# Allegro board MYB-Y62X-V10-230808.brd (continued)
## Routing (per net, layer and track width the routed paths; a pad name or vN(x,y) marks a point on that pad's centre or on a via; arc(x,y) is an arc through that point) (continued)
VDD_3V9: length 36.1
  TOP w0.381: R328.1 C177.1 v1(33.45,63.25)
  ART03 w0.381: v1(33.07,65.91) 33.45,65.53 v1(33.45,63.25)
  BOTTOM w0.381: R337.1 R336.1 ; R336.1 R342.1 R341.1 41.28,45.15 42.01,44.42 43.77,44.42 R340.1 R339.1 45.77,45.03 46.38,44.42 48.23,44.42 48.61,44.81 v1(48.61,48.97) ; R336.1 30.27,43.66 29.71,43.1 27.22,43.1 26.74,43.59 26.74,44.92 R338.1
  vias: v1(27.35,59.82) v1(27.35,59.18) v1(27.99,59.82) v1(27.99,59.18) v1(32.43,67.18) v1(32.43,66.55) v1(32.43,65.91) v1(33.07,67.18) v1(33.07,66.55) v1(44.75,59.31) v1(45.39,59.31) v1(46.02,59.31) v1(46.66,59.31) v1(46.66,58.67) v1(46.66,58.04)
VDD_5V: length 87
  TOP w0.203: U53.7 v1(151.81,49.78)
  TOP w0.381: R10.1 v1(34.46,29.9) ; v1(41.63,33.59) R13.1 40.62,33.66 R14.1 ; D59.1 v1(149.27,16.13) ; D58.1 147.62,15.88 v1(147.24,16.26) ; v1(130.6,22.73) 130.6,22.32 F3.2 131.62,22.32 v1(131.62,22.73) ; v1(125.55,24.21) 125.55,23.8 F2.2 124.53,23.8 v1(124.53,24.21) ; R531.1 144.77,51.33 145.21,51.77 147.82,51.77 148.64,50.95 152.35,50.95 152.77,50.53 C281.1 151.94,49.91 v1(151.81,49.78) ; R324.1 v1(43.23,62.74)
  ART03 w0.381: v1(43.23,62.74) 46.45,62.74 47.04,63.32 v1(47.04,66.93) ; v1(164.26,42.42) 163.75,42.93 161.72,42.93 160.42,44.22 158.85,44.22 154.61,48.46 153.36,48.46 152.04,49.78 v1(151.81,49.78)
  ART03 w0.508: v1(22.91,64.72) 22.65,64.97 21.71,64.97 20.95,65.74 20.95,68.99 19,70.94 19,78.41 21.26,80.67 v1(21.26,84.2)
  BOTTOM w0.381: v1(147.24,16.26) 147.62,15.88 C90.1 ; 48.43,39.24 R17.1 ; v1(74.82,97.16) 75.08,96.9 76.52,96.9 R21.1 ; R530.1 151.32,50.27 v1(151.81,49.78) ; v1(43.91,42.14) 43.71,41.94 43.71,34.24 43.06,33.59 v1(41.63,33.59)
  vias: v1(22.91,64.08) v1(23.54,64.72) v1(23.54,64.08) v1(24.15,64.74) v1(24.15,64.11) v1(43.91,42.75) v1(44.52,42.75) v1(44.52,42.14) v1(45.11,42.75) v1(45.11,42.14) v1(45.72,42.75) v1(45.72,42.14) v1(47.04,68.2) v1(47.04,67.56) v1(47.37,40.97) v1(47.37,40.36) v1(47.67,68.2) v1(47.67,67.56) v1(47.67,66.93) v1(47.98,40.97) v1(47.98,40.36) v1(55.93,26.92) v1(55.93,26.29) v1(56.56,26.92) v1(56.56,26.29) v1(70.99,98.83) v1(70.99,98.22) v1(71.62,98.83) v1(71.62,98.22) v1(111.43,100.46) v1(111.43,99.95) v1(111.93,100.46) v1(111.93,99.95) v1(164.26,41.91) v1(164.77,42.42) v1(164.77,41.91) v1(170.86,99.82) v1(171.62,99.82) v1(171.62,99.19) v1(171.62,98.55)
VDD_5V_SW:
  vias: v1(32.2,33.86) v1(32.86,33.86) v1(33.57,37.97) v1(33.57,37.39)
VDD_12V: length 44.5
  TOP w0.381: R4.1 45.13,76.33 45.89,77.09 v1(45.89,78.11) ; v1(36.57,32.69) 36.57,31.32 38.1,29.79 39.35,29.79 39.73,30.18 R11.1
  ART03 w0.381: v1(45.89,78.11) 45.26,78.74 44.34,78.74 40.79,82.3 36.37,82.3 35.84,81.76 v1(29.94,81.76)
  BOTTOM w0.381: v1(21.18,36.07) 21.21,36.04 26.51,36.04 30.96,31.6 35.48,31.6 v1(36.57,32.69)
  vias: v1(10.59,23.75) v1(10.59,23.24) v1(10.59,22.73) v1(11.1,23.75) v1(11.1,23.24) v1(11.1,22.73) v1(11.6,23.75) v1(11.6,23.24) v1(11.6,22.73) v1(12.11,23.75) v1(12.11,23.24) v1(12.11,22.73) v1(12.44,89.59) v1(12.44,88.95) v1(13.08,89.59) v1(13.08,88.95) v1(17.06,100.97) v1(17.06,100.33) v1(17.7,100.97) v1(17.7,100.33) v1(20.52,37.24) v1(20.52,36.65) v1(20.52,36.07) v1(21.18,37.24) v1(21.18,36.65) v1(22.14,84.2) v1(22.78,84.2) v1(29.28,82.91) v1(29.28,82.32) v1(29.28,81.74) v1(29.94,82.93) v1(29.94,82.35)
VDD_485_5V: length 2
  TOP w0.381: v1(133.02,110.24) 132.57,109.79 R267.1
  TOP w0.508: R279.1 v1(121.46,109.43)
  vias: v1(111.68,106.05) v1(111.68,105.41) v1(112.31,106.05) v1(112.31,105.41) v1(114.35,107.31) v1(114.35,106.81) v1(114.98,107.31) v1(127.05,107.31) v1(127.05,106.81) v1(127.68,107.31)
VDD_AUDIO_3V3: length 1.2
  TOP w0.254: v1(41.32,21.59) 41.45,21.72 U27.5
  vias: v1(38.35,25.73) v1(38.88,25.73) v1(39.42,26.26) v1(39.42,25.73)
VDD_BLE_3V3: length 56.4
  TOP w0.381: R74.1 R76.1 R72.1 R71.1 R69.1 R70.1 v2(41.64,109.54) 42.59,110.49 R77.1 ; R73.1 64.88,111.44 v2(64.56,111.12) 64.56,107.26 66.14,105.69 66.14,98.98 64.72,97.56 ; v2(56.43,93.34) C271.1 R511.1 54.66,93.92 Y6.4
  ART03 w0.381: v1(58.34,96.65) 58.34,96.39 56.43,94.49 v2(56.43,93.34)
  BOTTOM w0.381: v2(41.64,109.54) 43.23,111.12 v2(64.56,111.12)
VDD_CAN_5V:
  vias: v1(141.02,106.68) v1(141.65,106.68) v1(142.29,106.68) v1(142.29,106.05) v1(152.45,106.81) v1(153.08,106.81) v1(153.72,106.81) v1(153.72,106.17) v1(169.59,105.16) v1(170.23,105.16) v1(170.86,105.16) v1(171.5,105.16)
VDD_IN_GND:
  vias: v1(30.53,15.75) v1(30.53,15.11) v1(31.16,15.75) v1(31.16,15.11) v1(31.8,15.75) v1(31.8,15.11)
VDD_LVD_5V: length 11.6
  TOP w0.381: C79.1 21.86,89.59 C80.1 20.31,89.59 v1(19.85,90.05) Q3.3
  BOTTOM w0.381: v1(19.85,90.05) 19.85,88.78 20.49,88.14 20.49,86.74 19.86,86.11 18.72,86.11 18.08,85.47 v1(18.08,84.07)
  vias: v1(17.45,84.07) v1(17.45,83.44) v1(17.57,53.85) v1(17.57,53.21) v1(18.08,83.44) v1(18.21,53.85) v1(18.21,53.21)
VDD_MMC1_SD: length 10.3
  TOP w0.305: 79.97,105.17 C54.1
  TOP w0.381: v2(79.04,103.63) R36.1 R35.1 R34.1 ; R40.1 R39.1 R38.1 R37.1 82.07,104.29 81.07,105.28 FB1.2
  BOTTOM w0.381: v2(79.04,103.63) 79.04,104.65 v2(80.06,105.66)
  vias: v1(80.18,109.86) v1(80.18,109.22) v1(81.33,108.71) v2(80.44,105.92) v2(80.95,105.93)
VDD_PHY1_1V1: length 25.6
  TOP w0.203: U33.22 93.73,33.76 v1(93.79,33.81)
  BOTTOM w0.381: C211.1 92.85,32.84 91.79,31.78 88.24,31.78 86.84,33.17 86.84,39.48 v1(86.44,39.88)
  BOTTOM w0.508: C211.1 93.01,33.81 v1(93.79,33.81) 93.85,33.76 93.85,28.76 94.26,28.35 96.08,28.35 96.73,27.7 v1(96.73,27.18)
  vias: v1(85.37,39.88) v1(85.87,39.88) v1(96.16,27.2)
VDD_PHY1_3V3: length 25.1
  TOP w0.203: U33.30 90.07,36 v1(89.87,36.2) 89.67,36 U33.31
  TOP w0.381: R365.1 v1(82.89,40.01) ; R365.1 R370.1 ; R365.1 R364.1
  BOTTOM w0.381: v1(83.49,34.54) 83.44,34.54 81.01,36.97 81.01,39.46 81.56,40.01 v1(82.89,40.01) 83.68,40.79 86.66,40.79 87.6,39.85 87.6,36.27 88.38,35.49 C215.1 C216.1 90.13,35.94 v1(89.87,36.2)
  vias: v1(83.49,33.91) v1(83.99,34.16)
VDD_PHY2_1V1: length 26.8
  TOP w0.203: U37.22 117.03,33.76 v1(117.09,33.81)
  BOTTOM w0.381: v1(119.55,26.8) 119.55,29.31 117.93,30.94 117.93,32.97 v1(117.09,33.81) 116.31,33.81 C226.1 116.02,32.18 115.64,31.8 111.58,31.8 110.84,32.54 110.84,33.68 107.69,36.83 107.69,38.73 108.48,39.52 v1(108.48,40.03)
  BOTTOM w0.508: v1(109.65,40.03) v1(110.18,40.03)
  vias: v1(119.02,26.8)
VDD_PHY2_3V3: length 22.2
  TOP w0.203: U37.31 112.97,35.87 v1(113.19,36.09) 113.37,35.92 U37.30
  TOP w0.381: R405.1 R400.1 R399.1 105.33,39.31 v1(105.33,40.01)
  BOTTOM w0.381: v1(113.19,36.09) 113.42,35.86 C235.1 ; v1(103.64,37.59) v1(104.28,37.59) 104.34,37.65 104.34,39.37 104.97,40.01 v1(105.33,40.01) 105.33,40.23 105.84,40.74 108.63,40.74 109.06,40.31 109.06,39.22 108.28,38.43 108.28,37.21 110,35.49 C233.1
  BOTTOM w0.508: C233.1 C235.1
VDD_RTC:
  vias: v1(115.97,64.82) v1(116.53,64.82) v1(123.39,61.19) v1(124.05,61.19)
VDD_SOM_3V3: length 187.2
  TOP w0.381: R227.1 R231.1 R230.1 ; v2(142.39,46.41) 145.64,46.41 146.77,45.27 R222.1 R228.1 R223.1 R224.1 R225.1 R226.1 155.37,45.82 v2(155.14,46.05) ; R230.1 v1(129.59,39.4) ; R230.1 R220.1 R219.1 R218.1 R229.1 119.76,40.2 119.38,40.58 119.38,41.94 116.94,44.37 116.94,50.24 114.96,52.22 v2(109.98,52.22) ; v2(86.58,41.76) 84.88,41.76 83.92,40.79 80.9,40.79 75.69,35.59 65.25,35.59 63.88,34.21 v1(51.93,34.21) ; R217.1 R221.1 157.86,51.31 156.69,50.14 156.69,48.72 158.16,47.24 R216.1 158.8,46.51 159.64,45.67 v2(159.64,43.46)
  TOP w0.508: v1(104.99,81.88) U43.L43
  ART03 w0.381: v2(159.64,43.46) 159.2,43.03 156.97,43.03 155.14,44.86 v2(155.14,46.05) ; v2(109.98,52.22) 109.98,53.01 105.96,57.02 105.96,72.49 105.13,73.33 105.13,75.39 105.63,75.9 105.63,78.31 107.06,79.73 107.06,80.85 106.03,81.88 v1(104.99,81.88) ; v2(142.39,46.41) 141.3,46.41 134.29,39.4 v1(129.59,39.4)
  BOTTOM w0.381: v2(109.98,52.22) 105.33,47.57 90.85,47.57 90.32,48.11 88.13,48.11 87.47,47.45 87.47,42.65 v2(86.58,41.76) ; R573.1 v1(51.93,34.21)
VDD_SOM_5V: length 37.4
  TOP w0.381: v1(61.36,86.79) 58.77,86.79 47.04,75.06 39.44,75.06 38.78,75.72 R3.1
  BOTTOM w0.381: v1(66.77,92.35) 66.77,89.99 63.57,86.79 v1(61.36,86.79)
VDD_SOM_5V_R: length 10.8
  TOP w0.381: R8.1 44.95,79.63 R7.1 45.39,80.07 v2(45.39,80.52)
  ART03 w0.381: v2(45.39,80.52) 45.39,80.64 44.47,81.56 44.47,86.87 45.34,87.73 v2(46.22,87.73)
  vias: v1(69.01,97.99) v1(69.01,97.49) v1(69.03,96.98) v1(69.03,96.39) v1(69.57,97.99) v1(69.57,97.49) v1(69.57,96.98) v1(69.57,96.39) v2(46.22,88.24) v2(46.73,88.24) v2(46.73,87.73) v2(47.24,88.24) v2(47.24,87.73) v2(47.75,88.24) v2(47.75,87.73)
VDD_SOM_5V_SW:
  vias: v1(36.62,79.5) v1(37.13,79.5) v1(37.26,83.82) v1(37.77,83.82)
VDD_USB0_VBUS: length 7.6
  TOP w0.203: C154.1 v1(59.74,18.8) 59.54,18.6 U29.4
  TOP w0.254: J15.A9 57.26,8.06 v1(57.83,8.64) ; v1(54.02,8.38) 54.4,8.38 54.76,8.03 J15.A4 ; J15.B4 57,4.77 v1(57.45,4.32) ; J15.B9 v1(54.5,4.45)
  vias: v1(59.86,10.54) v1(59.86,9.65) v1(59.86,8.89) v1(60.6,8.89) v1(62.91,23.24) v1(62.91,22.48) v1(62.91,21.84) v1(63.55,21.84)
VDD_USB_1V8: length 8.1
  TOP w0.254: U28.3 v1(125.55,31.34) ; U28.29 v1(136.18,28.84) ; U28.26 135.78,27.34 v1(136.19,26.92)
  BOTTOM w0.381: C148.1 126.23,30.26 C152.1 125.58,31.37 v1(125.55,31.34) ; C150.1 135.36,29.05 C149.1 136.06,28.96 v1(136.18,28.84) ; C151.1 v1(136.19,26.92)
  vias: v1(122.6,32.89) v1(123.49,32.89)
VDD_USB_PLL: length 4.5
  TOP w0.254: 125.65,28.57 125.88,28.34 U28.9
  TOP w0.381: 125.65,28.57 123.25,30.97 FB7.2
VDD_USIM1: length 90.8
  TOP w0.381: v1(71.86,102.3) 69.55,102.3 68.02,103.83 v1(67.97,103.83)
  ART03 w0.381: v1(49.75,75.23) 45.22,79.76 44.37,79.76 43.61,80.52 43.61,95.45 54.96,106.81 65.3,106.81 67.97,104.13 v1(67.97,103.83)
  BOTTOM w0.305: v1(49.75,75.23) 49.75,65.95 48.69,64.9 38.91,64.9 36.25,62.24 J19.36
  BOTTOM w0.381: R322.1 v1(71.86,102.3) ; v1(67.97,103.83) 67.97,102.68 67.59,102.3 R323.1 65.99,102.3 TP15.1
VDD_USIM2: length 89
  TOP w0.381: v1(87.96,102.3) v1(91.55,102.3)
  ART03 w0.381: v1(52.62,72.26) 56.77,76.4 56.77,87.05 56.21,87.6 56.21,92.3 60.96,97.05 65.73,97.05 68.22,99.54 69.95,99.54 70.51,100.1 74.72,100.1 76.02,98.81 80.03,98.81 83.53,102.3 v1(87.96,102.3)
  BOTTOM w0.305: J19.48 39.25,59.11 39.55,59.41 42.57,59.41 43.86,60.71 49.27,60.71 52.62,64.06 v1(52.62,72.26)
  BOTTOM w0.381: R331.1 v1(91.55,102.3) ; R334.1 v1(87.96,102.3)
VDDA_PHY1_1V1: length 5.1
  TOP w0.203: U33.4 v2(88.87,28.57) ; v1(85.94,30.35) 86.14,30.56 U33.47 ; U33.9 v2(90.87,28.57)
  BOTTOM w0.381: v1(85.94,30.35) 86.39,30.8 C219.1 ; C217.1 90.89,28.59 v2(90.87,28.57) ; v2(88.87,28.57) 88.86,28.59 C218.1
  vias: v1(94.69,27.15) v1(95.25,27.15)
VDDA_PHY1_3V3: length 13.9
  TOP w0.203: U33.12 92.07,28.78 92.28,28.57 v1(92.29,28.57) ; U33.1 87.67,28.92 v1(87.33,28.57)
  TOP w0.381: FB8.2 84.64,28.57 v1(87.33,28.57)
  ART03 w0.381: v1(92.29,28.57) 92.25,28.57 91.54,29.29 88.04,29.29 v1(87.33,28.57)
  BOTTOM w0.381: v1(92.29,28.57) 92.03,28.83 C213.1 ; C212.1 87.71,28.96 v1(87.33,28.57)
VDDA_PHY2_1V1: length 5.1
  TOP w0.203: v1(109.23,30.35) 109.43,30.56 U37.47 ; U37.4 v2(112.17,28.57) ; U37.9 v2(114.17,28.57)
  BOTTOM w0.381: v2(112.17,28.57) 112.15,28.59 C237.1 ; v1(109.23,30.35) 109.68,30.8 C238.1 ; C236.1 114.18,28.59 v2(114.17,28.57)
  vias: v1(116.84,28.47) v1(117.39,28.45)
VDDA_PHY2_3V3: length 28.5
  TOP w0.203: v1(110.31,29.01) 110.76,29.01 110.97,29.21 U37.1 ; U37.12 115.37,29.16 115.57,28.96 v1(115.87,28.96)
  TOP w0.381: v1(101.9,37.43) 101.86,37.47 ; v1(110.31,29.01) 108.58,29.01 106.97,27.39 103.21,27.39 101.39,29.21 v1(101.39,37.47)
  ART03 w0.381: v1(101.9,37.43) 101.86,37.47 v1(101.39,37.47) ; v1(110.31,29.01) 111.07,29.77 115.06,29.77 v1(115.87,28.96)
  BOTTOM w0.381: v1(110.31,29.01) 110.58,29.28 C232.1 ; C231.1 115.65,28.96 v1(115.87,28.96)
32.7K_CLK: length 4.5
  TOP w0.152: R512.2 R513.1 C272.1 53.84,97.48 55.04,98.68 U47.31
ANTCTL1: length 4
  BOTTOM w0.152: J19.61 42.5,49.57 41.07,48.13 40.69,48.13 TP23.1
ANTCTL2: length 3.6
  BOTTOM w0.152: J19.63 43,49.43 TP24.1
AP2SDX_STATUS: length 15.3
  BOTTOM w0.152: R343.1 46.78,47.93 48.69,49.83 48.69,52.96 47.54,54.1 46.27,54.1 44.25,56.13 J19.68
AUD_MCASP0_ACLKX: length 30.3
  TOP w0.152: U54.3 68.89,31.66 68.42,31.19 68.42,30.12 67.89,29.59 63.42,29.59 60.66,32.35 50.3,32.35 48.43,30.48 R292.1
AUD_MCASP0_AFSX: length 31
  TOP w0.152: R294.1 49.32,30.48 50.56,31.72 60.53,31.72 63.17,29.08 68.27,29.08 68.91,29.72 v2(68.91,31.01) ; v2(69.54,32.99) 70.15,33.61 U54.6
  BOTTOM w0.152: v2(69.54,32.99) 69.54,31.65 v2(68.91,31.01)
AUD_MCASP0_AXR0: length 24.4
  TOP w0.152: R293.1 46.66,30.35 49.77,33.47 64.55,33.47 65.34,34.26 U54.10
AUD_MCASP0_AXR1: length 23.3
  TOP w0.152: R295.1 47.54,30.48 50.01,32.94 64.51,32.94 65.15,32.31 U54.13
AUD_MIC: length 23
  TOP w0.254: R297.1 C127.1 46.27,16.25 46.27,13.13 46.71,12.7 46.71,6.55 46.02,5.87 42.44,5.87 40.15,3.58 J14.4
AUDIO_GND: length 166.1
  TOP w0.254: C128.2 38.21,24.86 37.59,25.48 36.29,25.48 33.45,22.63 33.45,11.43 35.23,9.65 36.37,9.65 37.13,8.89 v1(37.13,7.37) ; v1(47.14,5.82) 47.14,13.03 46.83,13.34 46.83,14.22 v1(48,15.39) ; v2(45.46,18.21) 45.46,13.16 46.2,12.42 46.2,6.99 45.64,6.43 42.01,6.43 39.75,4.17 v2(37.16,4.17) ; R298.2 35.53,20.57 v1(35.48,20.52) 34.72,19.76 34.72,14.73 v1(35.48,13.97) ; v1(42.46,12.7) 41.19,13.97 v1(35.48,13.97) ; U27.7 41.98,20.72 v1(41.58,20.32) ; v1(35.48,13.97) 34.84,13.34 34.84,11.56 35.73,10.67 37.13,10.67 38.53,9.27 v1(38.53,7.37) ; v2(37.13,3.05) 40.48,3.05 42.69,5.26 45.28,5.26 45.53,5.02 R570.2 ; R569.2 v1(42.08,17.91)
  TOP w0.381: v1(48,15.39) 48.62,16.01 C130.2 v1(49.24,15.41) 49.48,15.41 FB6.2 50.08,15.98 v1(50.62,15.44) ; v1(43.73,13.84) 41.96,15.62 C129.2 ; C128.2 v1(39.04,24.77) ; R570.2 v1(47.14,5.82)
  BOTTOM w0.381: v1(37.13,7.37) 37.13,9.5 35.48,11.15 v1(35.48,13.97) v1(35.48,20.52) ; v1(43.73,13.84) 42.08,15.49 v1(42.08,17.91) ; v1(43.73,13.84) 46.96,13.84 ; v1(43.73,13.84) 42.59,12.7 v1(42.46,12.7) 42.46,9.3 40.53,7.37 v1(38.53,7.37) ; v1(48,15.39) 46.96,14.35 46.96,13.84 ; 46.96,13.84 47.47,13.34 47.47,6.15 v1(47.14,5.82) ; v2(37.13,3.05) 37.16,3.07 v2(37.16,4.17) ; v1(39.8,28.96) 40,28.75 40,25.15 39.62,24.77 v1(39.04,24.77) 39.04,22.86 v1(41.58,20.32) 42.21,19.68 C131.2 ; 48.69,16.03 48.28,16.43 48.28,18.45 47.62,19.11 C132.2 46.36,19.11 v2(45.46,18.21)
  vias: v1(38.53,28.96) v1(39.16,28.96)
AUDIO_I2C_SCL: length 3.6
  TOP w0.152: U27.29 44.5,25.02 44.88,25.4 v1(44.88,26.29) R290.2
  BOTTOM w0.254: R290.2 v1(44.88,26.29)
AUDIO_I2C_SDA: length 3.5
  TOP w0.152: R291.2 v1(45.77,26.29) 45.5,26.02 U27.27
  BOTTOM w0.254: R291.2 v1(45.77,26.29)
AUDIO_LOUT_L: length 15.4
  TOP w0.254: J14.1 42,14.61 36.24,14.61 35.99,14.86 CT1.2 37.07,17.65 37.33,17.4 C129.1
AUDIO_LOUT_R: length 23.7
  TOP w0.254: C128.1 37.33,22.99 37.07,22.73 CT2.2 34.08,20.83 34.08,11.56 35.48,10.16 36.75,10.16 37.77,9.14 37.77,6.61 J14.2
AUDIO_MCLK: length 2.3
  TOP w0.254: U27.21 49.25,22.22 R288.2
AUDIO_SEL: length 8.8
  TOP w0.152: U54.1 75.44,30.36 JP1.1 77.52,32.44 77.52,34.29 78.02,34.8 R557.2
BOOTMODE00: length 2.3
  TOP w0.152: R206.2 R216.2 R232.1
BOOTMODE01: length 2.3
  TOP w0.152: R207.2 R233.1 R217.2
BOOTMODE02: length 2.3
  TOP w0.152: R234.1 R221.2 R208.2
BOOTMODE03: length 53.7
  TOP w0.152: R241.1 120.44,51.77 SW2.8 120.44,50.3 120.95,49.78 121.84,49.78 123.24,48.39 126.03,48.39 127.3,49.66 127.3,54.99 128.7,56.39 143.68,56.39 144.32,57.02 153.84,57.02 155.88,54.99 158.54,54.99 160.19,53.34 R209.2
BOOTMODE04: length 50.7
  TOP w0.152: R242.1 121.71,51.77 SW2.7 121.72,50.67 123.36,49.03 125.91,49.03 126.76,49.88 126.76,55.21 128.32,56.77 143.18,56.77 144.06,57.66 154.35,57.66 155.24,56.77 R210.2
BOOTMODE05: length 48.9
  TOP w0.152: R211.2 143.94,58.29 142.79,57.15 127.94,57.15 126.22,55.44 126.22,50.23 125.65,49.66 123.74,49.66 122.98,50.42 SW2.6 122.98,51.77 R243.1
BOOTMODE06: length 49.3
  TOP w0.152: R212.2 158.29,61.21 156.64,59.56 143.76,59.56 142.24,58.04 126.41,58.04 125.68,57.31 125.68,50.58 125.27,50.16 124.51,50.16 124.26,50.41 SW2.5 124.25,51.77 R244.1
BOOTMODE07: length 41.7
  TOP w0.152: R213.2 158.59,63.25 155.41,60.07 143.55,60.07 141.98,58.5 129.76,58.5 v2(129.59,58.67) ; v2(129.59,55.88) 129.21,55.88 128.7,55.37 128.7,54.61 129.14,54.17 R245.1 129.58,54.16 SW3.8
  ART03 w0.152: v2(129.59,58.67) v2(129.59,55.88)
BOOTMODE08: length 25.9
  TOP w0.152: R197.2 144.5,45.21 142.16,45.21 141.45,45.92 141.45,47.5 140.81,48.13 133.02,48.13 130.86,50.29 SW3.7 130.86,54.16 R246.1
BOOTMODE09: length 25.9
  TOP w0.152: R247.1 132.12,54.16 SW3.6 132.12,50.17 133.65,48.64 141.14,48.64 141.93,47.85 141.93,46.05 142.21,45.77 145.03,45.77 149.27,41.53 R199.2
BOOTMODE10: length 3.6
  TOP w0.152: R200.2 v2(150.29,43.69) R222.2
  BOTTOM w0.152: R222.2 v2(150.29,43.69)
BOOTMODE11: length 3.6
  TOP w0.152: R201.2 v2(151.3,43.69) R228.2
  BOTTOM w0.152: R228.2 v2(151.3,43.69)
BOOTMODE12: length 3.6
  TOP w0.152: R202.2 v2(152.32,43.69) R223.2
  BOTTOM w0.152: R223.2 v2(152.32,43.69)
BOOTMODE13: length 3.6
  TOP w0.152: R224.2 v2(153.34,43.69) R203.2
  BOTTOM w0.152: R224.2 v2(153.34,43.69)
BOOTMODE14: length 3.6
  TOP w0.152: R225.2 v2(154.35,43.69) R204.2
  BOTTOM w0.152: R225.2 v2(154.35,43.69)
BOOTMODE15: length 3.6
  TOP w0.152: R226.2 v2(155.37,43.69) R205.2
  BOTTOM w0.152: R226.2 v2(155.37,43.69)
BT_RST: length 121.6
  TOP w0.152: v2(127.86,81.18) 127.29,80.61 127.29,79.01 129.27,77.03 137.44,77.03 142.07,72.39 142.07,67.97 141.09,66.98 U42.7 ; v2(64,113.92) R73.2 63.99,111.96 U47.49
  ART03 w0.152: v2(127.86,81.18) 127.86,94.31 127.05,95.12 109.01,95.12 105.08,99.06 103.3,99.06 99.16,103.2 99.16,106.86 95.63,110.39 95.63,113.23 94.43,114.43 64.5,114.43 v2(64,113.92)
CAM_P1_MCLK: length 1.4
  BOTTOM w0.152: R152.2 161.77,49.03 Y1.3
CAM_RST: length 38.8
  TOP w0.152: R154.2 152.77,68.72 v2(153.46,68.72) U18.4
  ART03 w0.152: v2(162.1,44.58) 163.47,44.58 166.54,47.65 166.54,62.43 160.25,68.72 v2(153.46,68.72)
  BOTTOM w0.152: R150.2 v2(162.1,44.58)
CANH1: length 13.5
  TOP w0.508: R253.2 151.03,108.6 150.41,109.22 150.41,112.39 v2(151.24,113.22)
  BOTTOM w0.508: v2(151.24,113.22) D20.2 154.1,114.3 154.1,115.75 J13.2
CANH2: length 13.5
  TOP w0.508: R261.2 139.35,108.48 138.86,108.97 138.86,112.14 v2(139.93,113.22)
  BOTTOM w0.508: J13.5 141.59,114.67 D18.2 v2(139.93,113.22)
CANL1: length 9.9
  TOP w0.508: v2(155.81,113.22) 153.27,113.22 152.83,112.78 R254.2
  BOTTOM w0.508: J13.1 157.71,115.56 D21.2 v2(155.81,113.22)
CANL2: length 10.2
  TOP w0.508: R262.2 141.15,112.65 141.71,113.22 v2(144.51,113.22)
  BOTTOM w0.508: v2(144.51,113.22) D19.2 146.28,115.56 J13.4
CH_UART0_RXD: length 6.1
  TOP w0.152: U19.21 68.38,19.93 67.05,21.26 Q6.3
CH_UART0_TXD: length 8.6
  TOP w0.152: Q1.2 72.74,25.33 69.85,22.43 68.7,22.43 68.12,21.84 68.12,20.84 68.53,20.44 U19.20
CH_UART1_RXD: length 8.8
  TOP w0.152: Q8.3 76.12,27.18 74.47,27.18 74.21,26.92 74.21,22.53 73.83,22.15 72.61,22.15 72.36,21.89 U19.13
CH_UART1_TXD: length 4.9
  TOP w0.152: Q7.2 77.11,21.18 76.5,20.57 74.47,20.57 74.11,20.93 U19.12
CONFIG_0: length 4.6
  BOTTOM w0.152: R341.2 32.3,47.37 TP19.1 32.5,47.68 J19.21
CONFIG_1: length 4.4
  BOTTOM w0.152: J19.69 44.5,47.63 TP27.1 R340.2
CONFIG_2: length 4.5
  BOTTOM w0.152: R339.2 TP28.1 46,47.86 J19.75
CONFIG_3: length 4.6
  BOTTOM w0.152: R338.2 TP18.1 27.5,48.15 J19.1
CSI_PWDN: length 31.3
  TOP w0.152: v2(159.37,67.94) R153.2 157.77,68.71 U18.5
  ART03 w0.152: v2(159.37,67.94) 160.26,67.94 166.04,62.17 166.04,47.9 163.6,45.47 v2(162.1,45.47)
  BOTTOM w0.152: R151.2 v2(162.1,45.47)
CVCC_1V2: length 6.9
  TOP w0.254: U48.12 v2(147.89,35.94) ; U48.26 v2(143.81,31.36) ; U48.47 149.9,25.03 v2(149.91,25.02) ; v2(147.39,25.15) U48.42 ; U48.53 v2(152.9,25.15) ; U48.5 v2(151.4,35.98)
  BOTTOM w0.254: v2(147.89,35.94) 147.87,35.92 C285.1 ; C284.1 143.82,31.37 v2(143.81,31.36) ; v2(151.4,35.98) 151.43,35.94 C282.1
  BOTTOM w0.381: C286.1 152.83,25.21 v2(152.9,25.15) ; C287.1 v2(149.91,25.02)
  vias: v2(150.92,22.99) v2(151.43,22.99)
DEBUG_USB_CC1: length 7
  TOP w0.254: R249.1 68.25,12.51 67.99,12.26 67.99,10.61 68.25,10.36 D12.2 68.69,9.71 70.36,8.05 J12.A5
DEBUG_USB_CC2: length 11.3
  TOP w0.254: J12.B5 v1(71.6,4.45) ; D13.2 73.96,10.36 74.21,10.61 74.21,12.26 73.96,12.51 R250.1
  TOP w0.381: D13.2 v1(73.52,9.53)
  BOTTOM w0.381: v1(73.52,9.53) 72.94,8.95 72.94,5.79 v1(71.6,4.45)
DEBUG_USB_DM: length 16.4
  TOP w0.155: J12.A7 71.36,8.15 71.27,8.23 71.27,8.93 v2(71.44,9.09) 71.27,9.26 71.27,10 D10.2 71.27,10.57 71.27,11.18 L6.2 ; v2(70.52,3.62) 70.68,3.79 70.68,4.95 70.6,5.03 J12.B7
  BOTTOM w0.155: v2(71.44,9.09) 71.27,9.26 71.27,9.69 70.92,10.03 70.02,10.03 69.39,9.4 69.39,6.27 70.68,4.97 70.68,3.79 v2(70.52,3.62)
DEBUG_USB_DP: length 16.4
  TOP w0.155: J12.B6 71.1,5.03 71.01,4.95 71.01,3.79 v2(71.18,3.62) ; J12.A6 70.86,8.15 70.94,8.23 70.94,8.93 v2(70.78,9.09) 70.94,9.26 70.94,10 D11.2 70.94,10.57 70.94,11.18 L6.3
  BOTTOM w0.155: v2(70.78,9.09) 70.94,9.26 70.94,9.55 70.79,9.71 70.16,9.71 69.72,9.26 69.72,8.09 69.85,7.95 69.99,7.95 70.13,7.82 70.13,7.62 69.99,7.49 69.85,7.49 69.72,7.35 69.72,6.4 70.17,5.95 70.36,5.95 70.5,6.09 70.69,6.09 70.82,5.96 70.82,5.76 70.69,5.63 70.69,5.43 71.01,5.11 71.01,3.79 v2(71.18,3.62)
DEBUG_VBUS_5V: length 6
  TOP w0.254: J12.A9 v1(72.36,8.38) ; J12.B4 72.1,4.79 v1(72.44,4.45) ; v1(70.02,4.45) 69.6,4.87 J12.B9 ; J12.A4 69.86,7.91 69.39,8.38 v1(68.75,8.38)
  vias: v1(74.6,10.16) v1(74.6,9.53) v1(74.6,8.76) v1(74.72,16.64) v1(75.38,16.61) v1(75.36,8.76)
DRP: length 3.3
  BOTTOM w0.152: TP21.1 33.5,48.72 J19.25
DS: length 12.3
  TOP w0.152: R49.2 94.28,95.71 v2(94.56,95.99) 93.79,95.99 93.64,96.14 93.64,96.36 93.82,96.55 94.89,96.55 95.04,96.7 95.04,99.8 95.35,100.1 95.93,100.1 96.04,100.21 96.04,101.04 95.89,101.19 95.17,101.19 95.04,101.07 95.04,100.82 95.2,100.66 U55.C3
  BOTTOM w0.152: v2(94.56,95.99) 94.28,95.71 R49.2 R62.1
EN_VDD_3V3: length 5.7
  TOP w0.305: v2(54.61,40.13) 54.59,40.12 U3.8
  BOTTOM w0.381: v2(54.61,40.13) 53.7,40.13 R17.2 R19.1 C320.1 R573.2
ETH1_CONFIG_LDO0: length 7.2
  TOP w0.152: U33.36 87.67,35.59 87.47,35.79 84.82,35.79 v2(82.89,37.72) R365.2
  BOTTOM w0.152: R365.2 v2(82.89,37.72)
ETH1_LED_ACT: length 55.4
  TOP w0.152: v2(95.42,25.27) 95.42,23.72 95.58,23.56 D41.2 96.22,22.86 97.17,21.91 97.17,16.44 95.91,15.18 94.89,15.18 91.56,11.84 91.56,7.59 J22.12 ; U33.35 88.07,35.8 87.75,36.12 85.34,36.12 83.78,37.68 v2(83.78,37.72) R370.2
  BOTTOM w0.152: R370.2 v2(83.78,37.72) 83.78,36.92 85.01,35.69 85.01,32.64 84.12,31.75 84.12,26.67 85.01,25.78 94.92,25.78 v2(95.42,25.27)
ETH1_LED_LINK: length 49.3
  TOP w0.152: v2(83.51,25.25) 83.51,23.9 83.4,23.79 D40.2 82.63,17.4 89.24,10.79 89.24,7.49 87.23,5.49 J22.14 ; R364.2 v2(82,37.72) 85.16,34.56 U33.37
  BOTTOM w0.152: R364.2 v2(82,37.72) 84.58,35.14 84.58,32.97 83.51,31.9 v2(83.51,25.25)
ETH1_MD1_N: length 16.1
  TOP w0.13: U33.3 88.47,28.7 88.44,28.66 88.44,28.15 87.84,27.56 85.89,27.56 84.86,26.53 U32.6 84.86,24.44 85.3,24 85.3,22.48 85.19,22.36 85.19,20.9 85.59,20.49 85.59,18.44 85.15,18 84.98,17.92 84.92,17.74 J22.2
ETH1_MD1_P: length 16.1
  TOP w0.13: J22.1 84.66,18.27 84.84,18.21 84.95,18.27 85.26,18.58 85.26,20.36 84.86,20.76 U32.1 84.86,23.94 84.41,24.38 84.41,26.54 84.77,26.9 84.77,27.06 84.7,27.14 84.7,27.3 84.81,27.41 84.97,27.41 85.05,27.34 85.21,27.34 85.75,27.89 87.71,27.89 88.11,28.29 88.11,28.66 88.07,28.7 U33.2
ETH1_MD2_N: length 15.7
  TOP w0.13: J22.4 87.46,17.74 87.52,17.92 87.69,18 88.13,18.44 88.13,20.54 87.09,21.58 87.09,22.36 87.2,22.48 87.2,24 86.76,24.44 U32.4 86.76,26.39 86.91,26.54 88.22,26.54 89.64,27.96 89.64,28.66 89.67,28.7 U33.6
ETH1_MD2_P: length 15.6
  TOP w0.13: U33.5 89.27,28.7 89.31,28.66 89.31,28.09 89.06,27.85 88.8,27.85 88.66,27.7 88.66,27.54 88.66,27.44 88.09,26.87 87.82,26.87 87.66,27.03 87.43,27.03 87.27,26.87 86.68,26.87 86.31,26.5 86.31,24.38 86.76,23.94 U32.3 86.76,21.45 87.8,20.4 87.8,18.58 87.49,18.27 87.38,18.21 87.2,18.27 J22.3
ETH1_MD3_N: length 14.7
  TOP w0.13: U33.8 90.47,28.7 90.44,28.66 90.44,28.01 91.27,27.18 92.03,27.18 92.48,26.73 U34.6 92.48,24.44 92.92,24 92.92,22.48 92.81,22.36 92.81,20.69 93.21,20.28 93.21,18.44 92.77,18 92.6,17.92 92.54,17.74 J22.8
ETH1_MD3_P: length 14.7
  TOP w0.13: J22.7 92.28,18.27 92.46,18.21 92.57,18.27 92.88,18.58 92.88,20.15 92.48,20.55 U34.1 92.48,23.94 92.03,24.38 92.03,26.71 91.9,26.85 91.13,26.85 90.85,27.13 90.69,27.13 90.61,27.05 90.45,27.05 90.33,27.16 90.33,27.32 90.42,27.41 90.42,27.57 90.11,27.88 90.11,28.66 90.07,28.7 U33.7
ETH1_MD4_N: length 16
  TOP w0.13: U33.11 91.67,28.7 91.64,28.66 91.64,28.48 92.05,28.07 93.05,28.07 94.38,26.74 U34.4 94.38,24.44 94.82,24 94.82,22.48 94.71,22.36 94.71,21.66 95.16,21.21 95.72,21.21 96.1,20.83 96.1,18.79 95.31,18 95.14,17.92 95.08,17.74 J22.10
ETH1_MD4_P: length 16
  TOP w0.13: J22.9 94.82,18.27 95,18.21 95.11,18.27 95.77,18.92 95.77,20.69 95.58,20.88 95.03,20.88 94.38,21.53 U34.3 94.38,23.94 93.93,24.38 93.93,26.72 93.61,27.05 93.44,27.05 93.36,26.96 93.2,26.96 93.09,27.08 93.09,27.24 93.17,27.32 93.17,27.48 92.91,27.74 91.91,27.74 91.31,28.34 91.31,28.66 91.27,28.7 U33.10
ETH1_MRSTN: length 109.2
  TOP w0.152: v2(71.73,39.2) 71.88,39.05 U35.1 ; v2(139.52,59.41) 141.42,59.41 141.78,59.77 141.78,64.62 140.71,65.68 U42.9
  ART03 w0.152: v2(87.58,41.02) 87.6,41.02 89.12,39.5 94.87,39.5 95.96,40.59 98.98,40.59 101.27,38.3 109.34,38.3 110.03,37.62 113.48,37.62 114.09,37.01 117.14,37.01 117.84,37.71 118.63,37.71 118.89,37.44 126.87,37.44 127.55,38.13 139.06,38.13 139.8,38.86 139.8,43.08 143.2,46.48 143.2,48.13 v2(143.68,48.62)
  BOTTOM w0.152: v2(87.58,41.02) 87.3,41.3 83.18,41.3 82.64,40.75 80.96,40.75 78.38,38.18 72.92,38.18 72.67,38.43 R361.2 71.94,38.99 v2(71.73,39.2) ; v2(143.68,48.62) 139.52,52.78 v2(139.52,59.41)
ETH1_RST: length 24.2
  TOP w0.152: U35.4 v2(76.25,37.15) ; U33.13 93.06,30.16 93.21,30 v2(93.21,29.62)
  ART03 w0.152: v2(76.25,37.15) 80.12,37.15 81.83,35.43 83.64,35.43 84.76,34.32 84.76,33.66 88.03,30.38 92.45,30.38 v2(93.21,29.62)
  BOTTOM w0.152: v2(76.25,37.15) 76.19,37.21 R363.2 R25.1
ETH1_XTAL_I: length 7.1
  TOP w0.152: U33.45 84.34,31.36 C201.1 83.61,31.24 81.46,31.24 Y4.1
ETH1_XTAL_O: length 5
  TOP w0.152: Y4.3 83.09,30.76 C205.1 84.22,30.96 U33.46
ETH2_CONFIG_LDO0: length 7.4
  TOP w0.152: U37.36 110.97,35.51 110.79,35.69 108.09,35.69 v2(106.18,37.59) R400.2
  BOTTOM w0.152: R400.2 v2(106.18,37.59)
ETH2_LED_ACT: length 53.2
  TOP w0.152: U37.35 111.37,35.75 111.04,36.07 108.59,36.07 v2(107.07,37.59) R405.2 ; v2(116.96,24.51) 117.56,23.92 D43.2 119.87,22.17 119.87,16.57 118.48,15.18 117.59,15.18 114.25,11.84 114.25,7.59 J23.12
  BOTTOM w0.152: R405.2 v2(107.07,37.59) 107.07,26.45 108.5,25.02 116.46,25.02 v2(116.96,24.51)
ETH2_LED_LINK: length 48.1
  TOP w0.152: J23.14 109.93,5.49 111.93,7.49 111.93,10.79 105.29,17.44 D42.2 105.88,23.92 106.09,24.13 v2(106.09,24.51) ; U37.37 109.64,34.56 109.14,35.05 107.83,35.05 v2(105.29,37.59) R399.2
  BOTTOM w0.152: v2(106.09,24.51) 106.09,36.79 v2(105.29,37.59) R399.2
ETH2_MD1_N: length 16.7
  TOP w0.13: J23.2 107.62,17.74 107.68,17.92 107.89,18.02 108.29,18.42 108.29,20.58 107.85,21.02 107.85,22.36 107.96,22.48 107.96,24 107.52,24.44 U36.6 107.52,26.4 108.68,27.56 111.13,27.56 111.73,28.15 111.73,28.66 111.77,28.7 U37.3
ETH2_MD1_P: length 16.7
  TOP w0.13: U37.2 111.37,28.7 111.4,28.66 111.4,28.29 111,27.89 110.54,27.89 110.43,28 110.43,28.11 110.31,28.22 110.15,28.22 110.04,28.11 110.04,28 109.92,27.89 108.54,27.89 107.07,26.42 107.07,24.38 107.52,23.94 U36.1 107.52,20.89 107.96,20.45 107.96,18.56 107.7,18.29 107.53,18.21 107.36,18.27 J23.1
ETH2_MD2_N: length 16.5
  TOP w0.13: U37.6 112.97,28.7 112.93,28.66 112.93,27.7 111.82,26.6 109.61,26.6 109.42,26.41 U36.4 109.42,24.44 109.86,24 109.86,22.35 109.75,22.23 109.75,21.66 110.83,20.58 110.83,18.42 110.43,18.02 110.22,17.92 110.16,17.74 J23.4
ETH2_MD2_P: length 16.5
  TOP w0.13: J23.3 109.9,18.27 110.07,18.21 110.24,18.29 110.5,18.56 110.5,20.45 109.88,21.06 109.42,21.53 U36.3 109.42,23.94 108.97,24.38 108.97,26.16 109.09,26.28 109.09,26.54 109.47,26.92 110.18,26.92 110.33,27.08 110.57,27.08 110.72,26.92 110.96,26.92 111.11,27.08 111.35,27.08 111.5,26.92 111.69,26.92 112.02,27.26 112.02,27.47 112.19,27.64 112.4,27.64 112.6,27.84 112.6,28.66 112.57,28.7 U37.5
ETH2_MD3_N: length 14.1
  TOP w0.13: U37.8 113.77,28.7 113.73,28.66 113.73,27.63 114.5,26.86 U38.6 114.5,24.44 114.94,24 114.94,22.48 114.83,22.36 114.83,21.41 115.91,20.33 115.91,18.42 115.51,18.02 115.3,17.92 115.24,17.74 J23.8
ETH2_MD3_P: length 14.1
  TOP w0.13: U37.7 113.37,28.7 113.4,28.66 113.4,27.49 114.06,26.84 114.06,26.62 113.92,26.48 113.92,26.23 114.06,26.09 114.06,25.84 113.92,25.7 113.92,25.45 114.06,25.31 114.06,25.06 113.92,24.92 113.92,24.68 114.06,24.53 114.06,24.38 114.5,23.94 U38.1 114.5,21.27 114.77,21.01 114.77,20.77 114.92,20.61 115.16,20.61 115.58,20.19 115.58,18.56 115.32,18.29 115.15,18.21 114.98,18.27 J23.7
ETH2_MD4_N: length 15.2
  TOP w0.13: J23.10 117.78,17.74 117.84,17.92 118.05,18.02 118.7,18.67 118.7,20.5 117.87,21.34 117.19,21.34 116.73,21.79 116.73,22.36 116.84,22.48 116.84,24 116.4,24.44 U38.4 116.4,26.69 114.93,28.16 114.93,28.66 114.97,28.7 U37.11
ETH2_MD4_P: length 15.2
  TOP w0.13: U37.10 114.57,28.7 114.6,28.66 114.6,28.03 115.1,27.53 115.1,27.37 115,27.27 115,27.11 115.11,27 115.27,27 115.37,27.1 115.53,27.1 115.96,26.67 115.96,24.38 116.4,23.94 U38.3 116.4,21.66 117.05,21.01 117.73,21.01 118.37,20.36 118.37,18.81 117.86,18.29 117.69,18.21 117.52,18.27 J23.9
ETH2_MRSTN: length 100.2
  TOP w0.152: v2(128.71,59.32) 129.26,59.87 141.14,59.87 141.35,60.07 141.35,64.44 140.75,65.03 U42.10 ; v2(65.71,39.88) 65.71,39.24 65.93,39.02 U39.1
  ART03 w0.152: v2(128.71,59.32) 128.57,59.18 128.57,57.15 127.43,56.01 121.33,56.01 120.95,56.39 v2(109.77,56.39)
  BOTTOM w0.152: R396.2 65.99,38.96 65.71,39.24 v2(65.71,39.88) 65.71,40.51 69.52,44.32 69.52,46.63 71.6,48.72 77.85,48.72 78.63,47.93 85.19,47.93 86.51,49.25 91.16,49.25 91.64,48.77 103.02,48.77 105.58,51.33 105.58,53.95 106.55,54.91 108.3,54.91 v2(109.77,56.39)
ETH2_RST: length 67
  TOP w0.152: v2(116.63,29.59) 116.63,29.97 116.45,30.16 U37.13 ; U39.4 v2(70.24,37.12)
  BOTTOM w0.152: R26.1 R398.2 70.18,37.18 v2(70.24,37.12) 72.54,34.82 72.54,31.27 76.82,26.99 76.82,26.33 79.19,23.95 117.73,23.95 118.66,24.89 118.66,26.04 118.41,26.29 118.41,29.16 117.98,29.59 v2(116.63,29.59)
ETH2_XTAL_I: length 7.1
  TOP w0.152: Y5.1 104.75,31.24 106.9,31.24 C220.1 107.63,31.36 U37.45
ETH2_XTAL_O: length 5
  TOP w0.152: U37.46 107.52,30.96 C224.1 106.39,30.76 Y5.3
FPC_LVDS0_A0N: length 4.4
  BOTTOM w0.13: J6.8 15.84,50.6 15.93,50.51 18.6,50.51 R118.2
FPC_LVDS0_A0P: length 4.4
  BOTTOM w0.13: R110.2 18.66,50.19 15.93,50.19 15.84,50.1 J6.9
FPC_LVDS0_A1N: length 4.5
  BOTTOM w0.13: R113.2 18.63,48.77 17.4,48.77 17.15,49.01 15.93,49.01 15.84,49.1 J6.11
FPC_LVDS0_A1P: length 4.5
  BOTTOM w0.13: J6.12 15.84,48.6 15.93,48.69 17.02,48.69 17.26,48.44 18.63,48.44 R115.2
FPC_LVDS0_A2N: length 4.6
  BOTTOM w0.13: R119.2 18.63,46.99 17.53,46.99 17,47.51 15.93,47.51 15.84,47.6 J6.14
FPC_LVDS0_A2P: length 4.6
  BOTTOM w0.13: R121.2 18.63,46.66 17.39,46.66 16.87,47.19 15.93,47.19 15.84,47.1 J6.15
FPC_LVDS0_A3N: length 4.8
  BOTTOM w0.13: J6.20 15.84,44.6 15.93,44.51 16.62,44.51 17.7,43.44 18.63,43.44 R128.2
FPC_LVDS0_A3P: length 4.8
  BOTTOM w0.13: J6.21 15.84,44.1 15.93,44.19 16.48,44.19 17.56,43.11 18.63,43.11 R130.2
FPC_LVDS0_CLK0N: length 4.7
  BOTTOM w0.13: R123.2 18.63,45.21 17.65,45.21 16.85,46.01 15.93,46.01 15.84,46.1 J6.17
FPC_LVDS0_CLK0P: length 4.7
  BOTTOM w0.13: J6.18 15.84,45.6 15.93,45.69 16.72,45.69 17.52,44.89 18.63,44.89 R125.2
FPC_LVDS1_A0N: length 4
  BOTTOM w0.13: J5.8 15.71,79.43 15.8,79.34 16.27,79.34 17.19,80.27 17.74,80.27 R109.2
FPC_LVDS1_A0P: length 4
  BOTTOM w0.13: R111.2 17.74,79.94 17.33,79.94 16.41,79.02 15.8,79.02 15.71,78.93 J5.9
FPC_LVDS1_A1N: length 3.8
  BOTTOM w0.13: J5.11 15.71,77.93 15.8,77.84 16.68,77.84 17.19,78.36 17.74,78.36 R114.2
FPC_LVDS1_A1P: length 3.8
  BOTTOM w0.13: R116.2 17.74,78.03 17.33,78.03 16.81,77.52 15.8,77.52 15.71,77.43 J5.12
FPC_LVDS1_A2N: length 3.7
  BOTTOM w0.13: J5.14 15.71,76.43 15.8,76.34 16.57,76.34 16.81,76.58 17.74,76.58 R120.2
FPC_LVDS1_A2P: length 3.7
  BOTTOM w0.13: J5.15 15.71,75.93 15.8,76.02 16.71,76.02 16.95,76.25 17.74,76.25 R122.2
FPC_LVDS1_A3N: length 3.8
  BOTTOM w0.13: J5.20 15.71,73.43 15.8,73.34 16.87,73.34 17.19,73.03 17.74,73.03 R129.2
FPC_LVDS1_A3P: length 3.8
  BOTTOM w0.13: J5.21 15.71,72.93 15.8,73.02 16.74,73.02 17.06,72.7 17.74,72.7 R131.2
FPC_LVDS1_CLK0N: length 3.6
  BOTTOM w0.13: J5.17 15.71,74.93 15.8,74.84 17.78,74.84 R124.2
FPC_LVDS1_CLK0P: length 3.7
  BOTTOM w0.13: R126.2 17.7,74.52 15.8,74.52 15.71,74.43 J5.18
FULL_CARD_POWR_OFF_N: length 13.3
  BOTTOM w0.152: J19.6 28.75,53.85 30.65,51.94 30.65,47.75 29.38,46.48 R337.2
HDMI_CLK+: length 23.6
  TOP w0.13: U48.59 154.03,28.3 155.52,28.3 155.98,27.84 155.98,18.43 155.45,17.91 152.73,17.91 152.6,17.78 152.6,17.5 152.73,17.37 153.61,17.37 153.93,17.05 153.93,16.5 153.61,16.18 151.43,16.18 151.3,16.05 151.3,15.8 151.46,15.64 153.01,15.64 153.33,15.32 153.33,14.68 U52.C3
HDMI_CLK-: length 23.6
  TOP w0.13: U52.C4 153,14.64 153,15.19 152.87,15.32 151.32,15.32 150.97,15.67 150.97,16.19 151.3,16.51 153.47,16.51 153.6,16.64 153.6,16.92 153.47,17.05 152.59,17.05 152.27,17.37 152.27,17.92 152.59,18.24 153.42,18.24 153.58,18.39 153.94,18.39 154.09,18.24 155.32,18.24 155.65,18.57 155.65,18.92 155.52,19.05 155.52,19.44 155.65,19.57 155.65,19.96 155.52,20.09 155.52,20.47 155.65,20.6 155.65,20.99 155.52,21.12 155.52,21.51 155.65,21.64 155.65,22.03 155.52,22.16 155.52,22.55 155.65,22.68 155.65,27.7 155.38,27.97 154.08,27.97 U48.58
HDMI_CONN_CLKN: length 3.6
  TOP w0.13: J29.12 152.2,11.82 152.54,12.15 152.54,12.62 153.03,13.11 153.03,13.42 152.99,13.46 U52.A4
HDMI_CONN_CLKP: length 3.6
  TOP w0.13: U52.A3 153.39,13.46 153.35,13.42 153.35,12.98 152.86,12.48 152.86,12.16 153.2,11.82 J29.10
HDMI_CONN_SCL: length 51.7
  TOP w0.152: R522.2 v2(151.68,13.03) 150.7,12.04 J29.15 ; U53.8 150.15,50.28 149.78,49.91 v2(149.78,47.5)
  ART03 w0.152: v2(149.78,47.5) 149.78,47.35 144.45,42.01 144.45,30.86 143.68,30.1 143.68,24 145.72,21.97 145.72,19.3 146.86,18.16 149.02,18.16 151.68,15.49 v2(151.68,13.03)
  BOTTOM w0.152: R530.2 149.14,48.14 v2(149.78,47.5)
HDMI_CONN_SDA: length 51.1
  TOP w0.152: J29.16 150.2,12.43 v2(150.8,13.03) R523.2 ; v2(149.14,47.5) 149.14,50.04 148.9,50.28 U53.1 146.74,50.28 146.22,50.8 R531.2
  ART03 w0.152: v2(149.14,47.5) 143.94,42.29 143.94,38.48 143.18,37.72 143.18,23.37 145.27,21.28 145.27,18.99 146.6,17.65 148.76,17.65 150.8,15.62 v2(150.8,13.03)
HDMI_CONN_TX0N: length 3.4
  TOP w0.13: U52.A2 153.79,13.46 153.83,13.42 153.83,12.76 154.04,12.55 154.04,12.13 153.7,11.79 J29.9
HDMI_CONN_TX0P: length 3.4
  TOP w0.13: J29.7 154.7,11.84 154.36,12.18 154.36,12.69 154.15,12.9 154.15,13.42 154.19,13.46 U52.A1
HDMI_CONN_TX1N: length 3.8
  TOP w0.13: J29.6 155.2,11.9 155.54,12.23 155.54,12.65 155.86,12.97 156.13,12.97 156.24,13.08 156.24,13.42 156.2,13.46 U51.A4
HDMI_CONN_TX1P: length 3.8
  TOP w0.13: U51.A3 156.6,13.46 156.56,13.42 156.56,12.94 156.27,12.65 155.99,12.65 155.86,12.52 155.86,12.21 156.2,11.87 J29.4
HDMI_CONN_TX2N: length 3.4
  TOP w0.13: U51.A2 157,13.46 157.04,13.42 157.04,12.43 156.7,12.09 J29.3
HDMI_CONN_TX2P: length 3.4
  TOP w0.13: U51.A1 157.4,13.46 157.36,13.42 157.36,12.43 157.7,12.09 J29.1
HDMI_HPD: length 15
  TOP w0.152: Q2.2 149.23,17.04 R527.1 149.02,18.1 149.02,18.67 149.37,19.02 153.06,19.02 153.82,19.79 153.82,22.1 154.4,22.68 154.4,23.88 153.4,24.88 U48.54
HDMI_I2C_SCL: length 33.4
  TOP w0.152: R529.2 R532.1 v2(153.65,46.96) ; v2(151,25.22) 150.9,25.33 U48.49
  ART03 w0.152: v2(153.65,46.96) 151,46.96 145.46,41.43 145.46,28.04 147.19,26.31 150.19,26.31 151,25.5 v2(151,25.22)
HDMI_I2C_SDA: length 37.2
  TOP w0.152: R533.1 R528.2 144.77,47.51 145.21,47.07 149.98,47.07 v2(150.41,47.5) ; U48.48 150.4,25.04 v2(150.49,24.94)
  ART03 w0.152: v2(150.49,24.94) 150.49,25.22 149.91,25.81 147.06,25.81 144.95,27.91 144.95,41.76 150.41,47.22 v2(150.41,47.5)
HDMI_MCASP0_ACLKX: length 89.4
  TOP w0.152: v2(147.14,20.04) 147.27,20.04 R161.1 ; U54.2 v2(69.64,31.01)
  BOTTOM w0.152: v2(147.14,20.04) 147.14,19.41 146.53,18.8 144.45,18.8 143.94,19.3 141.14,19.3 140.38,20.07 130.58,20.07 129.56,21.08 127.1,21.08 126.08,22.1 116.4,22.1 115.77,21.46 85.14,21.46 84.53,22.07 77.87,22.07 69.64,30.3 v2(69.64,31.01)
HDMI_MCASP0_AFSX: length 87.4
  TOP w0.152: R162.1 147.19,20.97 147.19,20.69 v2(146.5,20) ; U54.5 70.29,32.96 v2(70.28,32.97)
  BOTTOM w0.152: v2(70.28,32.97) 70.28,30.43 78.1,22.61 128.95,22.61 131.04,20.51 140.7,20.51 141.42,19.79 144.29,19.79 144.51,20 v2(146.5,20)
HDMI_MCASP0_AXR: length 87.4
  TOP w0.152: R516.1 v2(146.48,20.57) ; U54.11 v2(68.25,33.61)
  BOTTOM w0.152: v2(146.48,20.57) 144.45,20.57 144.14,20.27 141.58,20.27 140.88,20.96 131.48,20.96 129.43,23.01 78.53,23.01 75.64,25.91 75.64,26.57 70.79,31.42 70.79,33.32 70.51,33.61 v2(68.25,33.61)
HDMI_MCLK: length 2.9
  TOP w0.152: R534.2 144.01,23.94 145.39,25.33 U48.38
HDMI_TX0+: length 24.1
  TOP w0.13: U48.62 154.48,29.86 154.57,29.77 156.36,29.77 156.97,29.16 156.97,28.71 157.1,28.58 157.61,28.58 157.93,28.26 157.93,27.73 157.61,27.41 157.1,27.41 156.97,27.28 156.97,27.02 157.1,26.89 157.61,26.89 157.93,26.57 157.93,26.04 157.61,25.71 157.1,25.71 156.97,25.58 156.97,25.33 157.1,25.2 157.61,25.2 157.93,24.87 157.93,24.34 157.61,24.02 157.1,24.02 156.97,23.89 156.97,23.69 157.1,23.56 157.33,23.56 157.65,23.24 157.65,22.71 157.33,22.39 157.1,22.39 156.97,22.26 156.97,17.98 154.15,15.16 154.15,15.03 154.19,14.99 U52.C1
HDMI_TX0-: length 24
  TOP w0.13: U48.61 154.48,29.36 154.57,29.44 156.22,29.44 156.64,29.02 156.64,28.57 156.96,28.25 157.48,28.25 157.61,28.12 157.61,27.86 157.48,27.73 156.96,27.73 156.64,27.41 156.64,26.88 156.96,26.56 157.48,26.56 157.61,26.43 157.61,26.17 157.48,26.04 156.96,26.04 156.64,25.72 156.64,25.19 156.96,24.87 157.48,24.87 157.61,24.74 157.61,24.48 157.48,24.35 156.96,24.35 156.64,24.03 156.64,23.56 156.96,23.24 157.2,23.24 157.33,23.11 157.33,22.85 157.2,22.72 156.96,22.72 156.64,22.4 156.64,19.16 156.51,19.04 156.51,18.65 156.64,18.52 156.64,18.11 156.04,17.52 155.81,17.52 155.56,17.26 155.56,17.03 155.31,16.78 155.08,16.78 154.83,16.53 154.83,16.3 154.58,16.05 154.35,16.05 154.1,15.8 154.1,15.57 153.83,15.3 153.83,15.03 153.79,14.99 U52.C2
HDMI_TX1+: length 23.9
  TOP w0.13: U51.C3 156.6,14.99 156.56,15.03 156.56,15.77 158.92,18.14 158.92,18.94 158.6,19.26 158.14,19.26 158.01,19.39 158.01,19.65 158.14,19.78 158.58,19.78 158.92,20.12 158.92,29.82 157.47,31.27 156.95,31.27 156.82,31.4 156.82,31.63 156.5,31.95 155.97,31.95 155.65,31.63 155.65,31.4 155.52,31.27 154.57,31.27 154.48,31.36 U48.65
HDMI_TX1-: length 23.9
  TOP w0.13: U51.C4 156.2,14.99 156.24,15.03 156.24,15.91 156.55,16.23 156.55,16.48 156.8,16.72 157.04,16.72 157.29,16.96 157.29,17.21 157.53,17.45 157.78,17.45 158.6,18.27 158.6,18.8 158.47,18.93 158,18.93 157.68,19.25 157.68,19.78 158,20.1 158.44,20.1 158.6,20.26 158.6,20.55 158.47,20.68 158.47,21.07 158.6,21.2 158.6,21.59 158.47,21.72 158.47,22.1 158.6,22.23 158.6,29.68 157.34,30.94 156.82,30.94 156.5,31.26 156.5,31.5 156.37,31.63 156.11,31.63 155.98,31.5 155.98,31.26 155.66,30.94 154.57,30.94 154.48,30.86 U48.64
HDMI_TX2+: length 23.8
  TOP w0.13: U51.C1 157.36,14.66 157.36,14.9 160.07,17.6 160.07,30.1 157.39,32.77 154.57,32.77 154.48,32.86 U48.68
HDMI_TX2-: length 23.9
  TOP w0.13: U51.C2 157.04,14.66 157.04,15.03 157.4,15.4 157.4,15.6 157.67,15.87 157.87,15.87 158.14,16.14 158.14,16.33 158.41,16.6 158.6,16.6 158.87,16.87 158.87,17.07 159.14,17.33 159.34,17.33 159.74,17.74 159.74,18.37 159.61,18.5 159.61,18.88 159.74,19.01 159.74,19.4 159.61,19.53 159.61,19.92 159.74,20.05 159.74,29.96 159.1,30.6 158.83,30.87 157.26,32.44 154.57,32.44 154.48,32.36 U48.67
HP_L: length 6
  TOP w0.254: U27.6 41.71,21.22 40.81,20.32 40.81,18.03 40.43,17.65 CT1.1
HP_R: length 3.3
  TOP w0.254: CT2.1 39.78,23.22 U27.2
HP_VGND: length 5.3
  TOP w0.254: R298.1 39.54,20.57 41.19,22.22 U27.4
HPD_DET: length 13.4
  TOP w0.152: J29.19 148.7,11.88 v2(148.15,12.42) ; v2(143.36,17.47) R525.1 R524.1
  BOTTOM w0.152: v2(143.36,17.47) 146.92,17.47 149.02,15.37 149.02,13.28 v2(148.15,12.42)
I2C_SCL_CSI: length 2.4
  TOP w0.152: U45.8 158.4,74.28 v2(158.67,74.55) R452.2
  BOTTOM w0.152: R452.2 v2(158.67,74.55)
I2C_SCL_CSI_1V8: length 34.5
  TOP w0.152: v2(159.37,72.26) R156.2 159.36,72.78 U45.5
  ART03 w0.152: v2(159.37,72.26) 160.93,72.26 163.66,69.54 163.66,66.23 167.05,62.84 167.05,47.5 167.56,46.99 v2(167.81,46.99)
  BOTTOM w0.152: v2(167.81,46.99) 167.81,45.97 167.49,45.65 J9.5
I2C_SDA_CSI: length 2.8
  TOP w0.152: U45.1 153.73,74.28 v2(153.46,74.55) R444.2
  BOTTOM w0.152: R444.2 v2(153.46,74.55)
I2C_SDA_CSI_1V8: length 46.4
  TOP w0.152: v2(162.86,71.25) 161.46,71.25 161.08,71.63 153.21,71.63 152.76,72.08 R157.2 152.77,72.78 U45.4
  ART03 w0.152: v2(162.86,71.25) 164.32,69.79 164.32,66.46 168.32,62.46 168.32,58.55 167.56,57.78 167.56,54.74 168.32,53.98 168.32,46.48 167.69,45.85 167.69,44.07 v2(167.94,43.81)
  BOTTOM w0.152: v2(167.94,43.81) 167.69,44.07 167.69,44.96 167.49,45.15 J9.4
I2S_DIN: length 3
  TOP w0.152: R293.2 46.66,26.04 46,25.38 U27.26
I2S_DOUT: length 3.1
  TOP w0.152: U27.25 46.5,24.99 47.54,26.04 R295.2
I2S_LRCLK: length 5
  TOP w0.152: R294.2 49.32,26.16 47.93,24.77 47.93,23.62 47.52,23.22 U27.23
I2S_SCLK: length 3.9
  TOP w0.152: U27.24 47.26,23.72 47.42,23.88 47.42,25.15 48.43,26.16 R292.2
IOVCC_3V3: length 72.3
  TOP w0.203: v2(151.81,49.02) 151.55,49.28 U53.6 ; U53.3 146.98,49.28 v2(146.35,49.91)
  TOP w0.254: v2(149.36,25.15) 149.4,25.18 U48.46 ; U48.3 v2(152.4,36.02) ; U48.21 v2(143.74,33.86)
  TOP w0.381: Y7.4 v2(141.35,22.11) R535.1 ; R514.1 v2(157.84,36.7) ; R528.1 v2(146.35,48.13) ; v2(146.35,49.91) C280.1 ; R529.1 v2(151.81,49.02) ; v2(152.98,19.66) 149.25,19.66 148.51,18.93 v2(148.26,18.93) Q2.3
  ART03 w0.381: v1(157.07,43.89) 157.07,45.09 154.28,47.88 152.9,47.88 151.81,48.97 v2(151.81,49.02)
  BOTTOM w0.381: v2(146.35,49.91) v2(146.35,48.13) 146.35,47.35 146.94,46.76 150.64,46.76 151.13,47.24 151.13,48.34 v2(151.81,49.02) ; R433.1 R537.1 153.97,20.04 153.59,19.66 v2(152.98,19.66) ; v2(148.26,18.93) 147.8,19.39 147.8,20.9 147.42,21.29 144.19,21.29 143.7,21.78 C293.1 141.68,21.78 v2(141.35,22.11) ; v2(149.36,25.15) 148.89,25.63 C288.1 ; v2(143.74,33.86) 143.79,33.91 C289.1 144.39,35.73 145.46,36.8 151.61,36.8 v2(152.4,36.02) 152.45,35.97 C290.1 156.5,35.36 v2(157.84,36.7) 158.01,36.87 158.01,39.78 157.07,40.72 v1(157.07,43.89)
  vias: v2(149.53,22.99) v2(150.03,22.99)
ISO_485: length 2
  TOP w0.508: R275.2 128.72,109.43 C117.2 ; R286.2 v1(117.01,109.43)
  vias: v1(104.06,103.5) v1(104.69,103.5) v1(106.22,103.38) v1(106.85,103.38) v1(112.82,102.62) v1(112.82,101.98) v1(113.46,102.62) v1(113.46,101.98) v1(114.35,110.24) v1(115.36,110.24) v1(116,110.24) v1(116.51,107.31) v1(117.01,108.58) v1(117.01,107.82) v1(117.78,107.82) v1(122.73,106.81) v1(123.49,106.81) v1(124.13,106.81) v1(124.63,107.7) v1(124.76,106.81) v1(125.4,109.35) v1(125.4,108.46) v1(125.4,107.7) v1(127.05,110.24) v1(128.06,110.24) v1(128.7,110.24) v1(129.08,107.31) v1(129.08,106.81) v1(129.59,107.31) v1(135.05,107.7) v1(135.17,106.81) v1(135.81,109.35) v1(135.81,108.46) v1(135.81,107.7) v1(135.94,106.81) v1(136.57,106.81) v1(137.21,106.81)
ISO_CAN: length 1.3
  TOP w0.508: C104.2 v1(151.36,109.28) ; C112.2 v1(139.68,109.22)
  vias: v1(140.25,107.7) v1(140.89,103.25) v1(141.4,103.25) v1(141.91,103.25) v1(142.41,103.25) v1(143.18,108.84) v1(143.18,108.2) v1(145.59,107.19) v1(147.11,107.19) v1(147.24,109.98) v1(147.75,107.19) v1(148.64,106.68) v1(149.27,106.68) v1(149.91,106.68) v1(149.91,105.92) v1(149.91,105.16) v1(149.91,104.39) v1(152.32,103.38) v1(152.83,103.38) v1(153.34,103.38) v1(153.84,103.38) v1(153.97,107.7) v1(154.61,108.97) v1(154.61,108.33) v1(154.61,107.7) v1(156.64,107.44) v1(156.64,106.81) v1(157.27,107.44) v1(157.27,106.81) v1(160.07,106.81) v1(160.7,106.81) v1(161.34,106.81) v1(161.34,106.05) v1(161.34,105.28) v1(161.34,104.52) v1(162.35,102.74) v1(163.11,102.74) v1(164.26,102.74) v1(165.15,102.74) v1(169.59,101.47) v1(170.23,101.47) v1(170.86,101.47) v1(171.5,101.47)
JTAG_CTI_RTCK: length 8.6
  TOP w0.152: 166.88,83.69 165.4,83.69 164.77,83.06 v2(162.35,83.06) ; R105.2 v2(160.7,80.64)
  ART03 w0.152: v2(162.35,83.06) 162.35,82.3 v2(160.7,80.64)
JTAG_CTI_TCK: length 21.1
  TOP w0.152: R106.1 R103.2 153.54,85.74 U12.1 155.73,85.74 156.38,85.09 156.38,83.95 155.37,82.93 154.61,82.93 154.35,82.68 154.35,82.17 154.59,81.93 U13.1 156.02,81.93 156.51,82.42 J4.11
JTAG_EMU_RSTN: length 130.2
  TOP w0.152: v2(69.64,47.88) 69.13,47.88 68.78,47.52 U43.45 ; R540.1 v2(162.61,78.99)
  ART03 w0.152: v2(162.61,78.99) 161.21,77.6 139.01,77.6 136.72,75.31 126.56,75.31 122.25,79.63 113.84,79.63 112.82,80.64 v2(112.82,81.15) ; v2(69.64,47.88) 72.56,50.8 91.44,50.8 91.94,50.29 102.28,50.29 103.37,51.38 103.37,78.56 v2(105.71,80.9)
  BOTTOM w0.152: v2(105.71,80.9) 105.96,81.15 v2(112.82,81.15)
JTAG_EMU_RSTN_R: length 3.6
  TOP w0.152: R540.2 R94.2 J4.15
JTAG_TDIS: length 7.1
  TOP w0.152: J4.4 169.41,87.5 168.78,86.87 164.32,86.87 R92.1
LAA_TX_EN: length 4.5
  BOTTOM w0.152: TP22.1 40.05,48.51 40.94,48.51 42,49.57 J19.59
LCD_B0: length 3.1
  TOP w0.152: U48.32 142.51,28.36 R163.2
LCD_B1: length 3
  TOP w0.152: R164.2 142.12,28.86 U48.31
LCD_B2: length 2.8
  TOP w0.152: U48.30 141.73,29.36 R165.2
LCD_B3: length 2.8
  TOP w0.152: U48.29 141.83,29.86 R166.2
LCD_B4: length 3
  TOP w0.152: U48.28 142.22,30.36 R167.2
LCD_B5: length 3.2
  TOP w0.152: U48.27 142.6,30.86 R168.2
LCD_B6: length 3.1
  TOP w0.152: U48.25 142.49,31.86 R169.2
LCD_B7: length 3.3
  TOP w0.152: R170.2 142.88,32.36 U48.24
LCD_DE: length 3.3
  TOP w0.152: U48.33 142.9,27.86 R194.2
LCD_G0: length 3.4
  TOP w0.152: R171.2 143.27,32.86 U48.23
LCD_G1: length 3.5
  TOP w0.152: U48.20 143.55,34.36 R172.2
LCD_G2: length 3.7
  TOP w0.152: R173.2 143.94,34.86 U48.19
LCD_G3: length 3.2
  TOP w0.152: R174.2 143.81,37.34 144.89,36.26 U48.18
LCD_G4: length 3
  TOP w0.152: R175.2 144.7,37.08 145.39,36.39 U48.17
LCD_G5: length 2.9
  TOP w0.152: U48.16 145.89,36.91 145.59,37.21 R176.2
LCD_G6: length 2.8
  TOP w0.152: U48.15 146.39,38.08 R177.2
LCD_G7: length 2.9
  TOP w0.152: U48.14 146.89,37.7 R178.2
LCD_HSYNC: length 3.4
  TOP w0.152: U48.34 143.29,27.36 R196.2
LCD_I2C_SCL: length 6
  TOP w0.152: U48.1 153.4,35.62 153.59,35.81 155.49,35.81 v2(157.27,37.59) R445.2
  BOTTOM w0.152: R445.2 v2(157.27,37.59)
LCD_I2C_SDA: length 5.9
  TOP w0.152: U48.2 152.9,36.01 153.08,36.2 154.99,36.2 v2(156.38,37.59) R489.2
  BOTTOM w0.152: R489.2 v2(156.38,37.59)
LCD_PCLK: length 3.7
  TOP w0.152: R198.2 143.23,33.79 143.23,33.68 143.55,33.36 U48.22
LCD_R0: length 3.1
  TOP w0.152: R179.2 147.39,37.31 U48.13
LCD_R1: length 3.1
  TOP w0.152: U48.11 148.39,37.29 R180.2
LCD_R2: length 3.3
  TOP w0.152: U48.10 148.89,36.77 R181.2
LCD_R3: length 3.7
  TOP w0.152: R182.2 150.76,37.63 150.38,37.63 149.4,36.64 U48.9
LCD_R4: length 4.1
  TOP w0.152: R183.2 151.36,37.21 150.67,37.21 149.9,36.44 U48.8
LCD_R5: length 4.6
  TOP w0.152: U48.7 150.4,36.3 150.92,36.83 151.56,36.83 152.07,37.34 152.51,37.34 R184.2
LCD_R6: length 5
  TOP w0.152: U48.6 150.9,36.17 151.18,36.45 151.68,36.45 152.19,36.96 153.14,36.96 R185.2
LCD_R7: length 5
  TOP w0.152: R186.2 153.83,36.63 152.37,36.63 151.9,36.15 U48.4
LCD_TP_INTN: length 106
  TOP w0.152: v2(140.31,68.94) U42.4
  ART03 w0.152: v2(154.86,20.57) 156.38,19.05 165.15,19.05 169.46,23.37 169.46,41.5 171.24,43.28 171.24,67.18 163.24,75.18 156,75.18 155.11,74.3 155.11,72.26 152.83,69.98 152.83,68.48 151.91,67.56 150.92,67.56 150.54,67.18 140.33,67.18 139.8,67.72 139.8,68.43 v2(140.31,68.94)
  BOTTOM w0.152: R190.1 155.3,20.57 v2(154.86,20.57)
LCD_TP_INTN_R: length 6.2
  TOP w0.152: v2(153.99,23.03) 153.95,23.07 153.95,23.52 152.4,25.07 U48.52
  BOTTOM w0.152: v2(153.99,23.03) 154.69,23.03 154.86,22.86 R433.2 R190.2
LCD_TP_RESET: length 107.5
  TOP w0.152: v2(140.31,68.29) U42.5
  ART03 w0.152: v2(140.31,68.29) 140.9,67.69 150.03,67.69 150.41,68.07 151.81,68.07 152.32,68.58 152.32,70.1 154.61,72.39 154.61,74.68 155.62,75.69 163.55,75.69 171.88,67.36 171.88,43.03 169.97,41.12 169.97,22.99 165.53,18.54 155.47,18.54 153.74,20.27 v2(153.31,20.27)
  BOTTOM w0.152: v2(153.31,20.27) 153.31,20.9 R191.1
LCD_TP_RESET_R: length 5.3
  TOP w0.152: U48.51 151.9,24.94 153.46,23.37 v2(153.46,22.71)
  BOTTOM w0.152: R191.2 152.93,22.17 v2(153.46,22.71) 153.97,22.2 R537.2
LCD_VSYNC: length 3.6
  TOP w0.152: U48.35 143.67,26.86 R195.2
LVDS0_CLKN: length 10.2
  TOP w0.13: U16.A4 18.99,61.79 18.96,61.76 12.35,61.76 12.04,62.08 12.04,62.43 12.18,62.58 J8.15
LVDS0_CLKP: length 10.2
  TOP w0.13: U16.A3 18.99,61.4 18.96,61.43 12.22,61.43 11.07,62.58 J8.16
LVDS0_D0N: length 10.9
  TOP w0.13: J8.7 12.14,54.58 11.98,54.42 11.98,54.22 12.48,53.72 15.92,53.72 17.46,55.26 18.93,55.26 18.97,55.3 U14.A2
LVDS0_D0P: length 10.9
  TOP w0.13: U14.A1 18.96,54.9 18.93,54.94 17.6,54.94 16.06,53.39 12.35,53.39 11.16,54.58 J8.8
LVDS0_D1N: length 10.3
  TOP w0.13: U14.A4 18.97,56.1 18.93,56.06 16.48,56.06 16.17,55.75 12.48,55.75 11.98,56.25 11.98,56.46 12.11,56.59 J8.9
LVDS0_D1P: length 10.4
  TOP w0.13: U14.A3 18.96,55.7 18.93,55.73 16.62,55.73 16.31,55.43 12.35,55.43 11.19,56.59 J8.10
LVDS0_D2N: length 12.1
  TOP w0.13: J8.11 12.19,58.59 12.01,58.41 12.01,58.14 12.41,57.75 16.26,57.75 17.45,58.93 17.45,59.94 18.46,60.96 18.96,60.96 18.99,61 U16.A2
LVDS0_D2P: length 12.2
  TOP w0.13: J8.12 11.1,58.59 12.27,57.42 16.4,57.42 17.77,58.79 17.77,59.81 18.6,60.63 18.96,60.63 18.99,60.6 U16.A1
LVDS0_D3N: length 10.7
  TOP w0.13: J8.17 12.17,64.59 12.04,64.46 12.04,64.08 12.49,63.63 17.7,63.63 18.73,62.59 U16.A6
LVDS0_D3P: length 10.7
  TOP w0.13: U16.A5 18.67,62.19 17.56,63.3 12.36,63.3 11.07,64.59 J8.18
LVDS0_I2C_SCL: length 154.1
  TOP w0.152: v2(129.46,59.31) 138.86,59.31 139.21,58.95 141.68,58.95 143.61,60.88 146,60.88 147.69,62.58 R438.2 R491.2
  ART03 w0.152: v2(129.46,59.31) 129.08,58.93 129.08,56.77 127.63,55.32 112.09,55.32 111.48,54.71 111.48,52.91 110.03,51.46 108.53,51.46 104.85,47.78 91.74,47.78 90.75,48.77 84.5,48.77 84.07,48.34 74.55,48.34 71.55,45.34 64.41,45.34 62.66,47.09 58.33,47.09 56.45,45.21 v2(50.72,45.21)
  BOTTOM w0.152: v2(50.72,45.21) 48.92,43.41 32,43.41 29.49,40.89 24.74,40.89 22.5,38.66 17.92,38.66 16.86,37.6 J6.34
